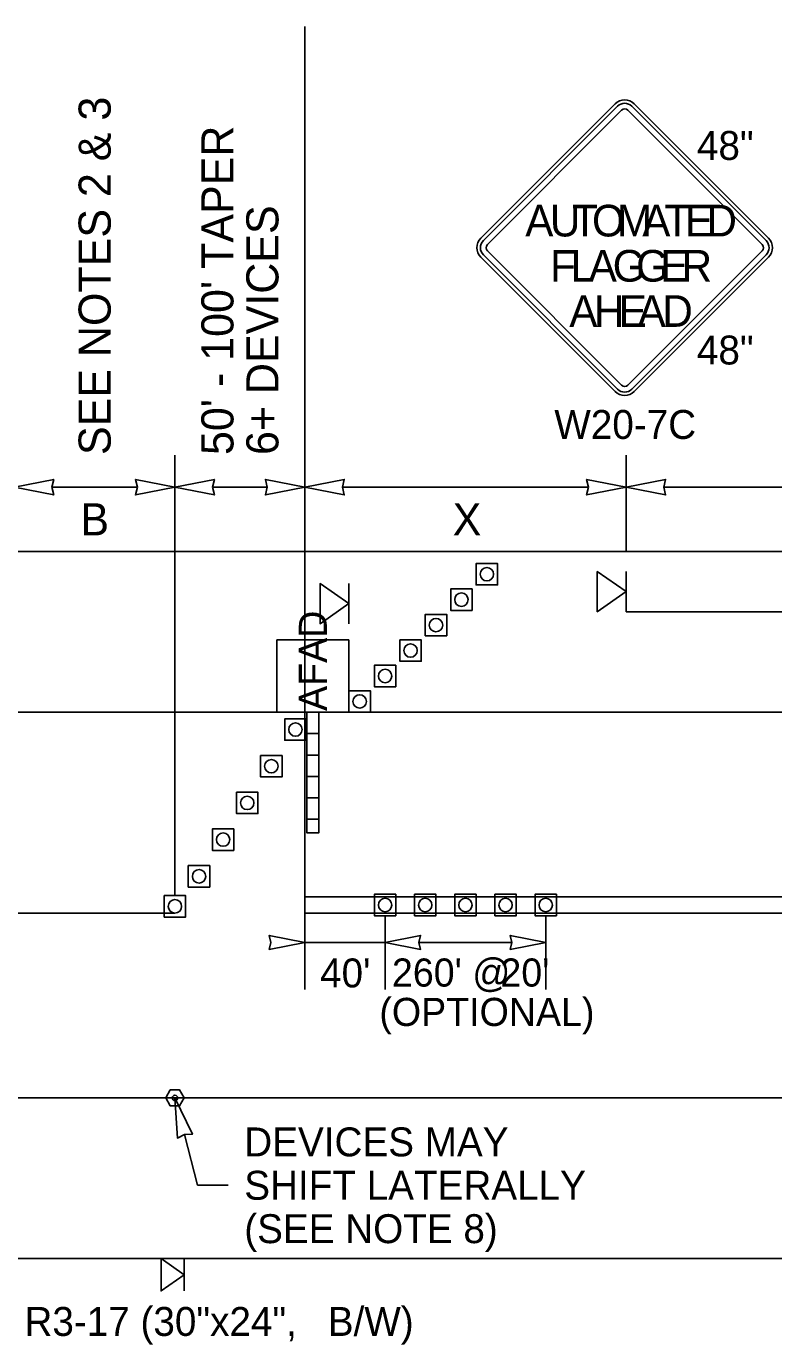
# Model space of a CAD drawing. Extents: x 99999.1 to 100095.7, y 99995 to 100010.7.
# Drawn here: x 100050.78 to 100052.641, y 100005.518 to 100008.799 of the extents above; entities that cross this region are included whole.
import ezdxf

# ---------------------------------------------------------------- set-up
doc = ezdxf.new("R2010")
doc.units = 0
for name, color, linetype in [('RD_ED_ShoulderPavedEdge', 7, 'Continuous'), ('RD_MK_LineDblYellowCenter', 7, 'Continuous'), ('RD_MK_LineEdgeWhite', 7, 'Continuous'), ('RD_MK_LineNoPass', 7, 'Continuous'), ('RD_MK_LineSkipCenter', 7, 'Continuous'), ('TR_SN_ConstructionSigns', 7, 'Continuous'), ('TR_WZ_AFAD', 7, 'Continuous'), ('TR_WZ_PortableSignMountBlk-Org', 7, 'Continuous'), ('TR_WZ_PortableSignMountBlk-Wht', 7, 'Continuous'), ('TR_WZ_TrafficCone', 7, 'Continuous'), ('TR_WZ_TubularMarker', 7, 'Continuous'), ('TR_WZ_WorkZoneDetails', 7, 'Continuous'), ('TR_WZ_WorkZoneTextCurrent', 7, 'Continuous')]:
    doc.layers.add(name, color=color, linetype=linetype)

msp = doc.modelspace()

# ---------------------------------------------------------------- linework, layer by layer
at = {"layer": 'RD_ED_ShoulderPavedEdge'}
for p, q in [((100040.1076, 100007.4923), (100055.6424, 100007.4923)), ((100040.1076, 100005.7323), (100055.6424, 100005.7323))]:
    msp.add_line(p, q, dxfattribs=at)
at = {"layer": 'RD_MK_LineDblYellowCenter'}
for p, q in [((100052.2733, 100006.6323), (100055.6631, 100006.6323)), ((100052.2733, 100006.5923), (100055.6218, 100006.5923))]:
    msp.add_line(p, q, dxfattribs=at)
at = {"layer": 'RD_MK_LineEdgeWhite'}
for p, q in [((100040.1076, 100007.0923), (100055.6424, 100007.0923)), ((100040.1076, 100006.1323), (100055.6424, 100006.1323))]:
    msp.add_line(p, q, dxfattribs=at)
at = {"layer": 'RD_MK_LineNoPass'}
msp.add_line((100051.4733, 100006.5923), (100052.2733, 100006.5923), dxfattribs=at)
at = {"layer": 'RD_MK_LineSkipCenter'}
for points in [[(100052.2733, 100006.6323), (100051.4733, 100006.6323)], [(100051.15, 100006.5923), (100043.4767, 100006.5923)]]:
    msp.add_lwpolyline(points, dxfattribs=at)
at = {"layer": 'TR_SN_ConstructionSigns'}
for p, q in [((100052.2461, 100008.6062), (100051.912, 100008.2721)), ((100052.2521, 100008.6002), (100051.918, 100008.2661)), ((100051.9279, 100008.2561), (100052.262, 100008.5903)), ((100052.2779, 100008.5903), (100052.612, 100008.2561)), ((100052.622, 100008.2661), (100052.2879, 100008.6002)), ((100052.6279, 100008.2721), (100052.2938, 100008.6062)), ((100051.918, 100008.2303), (100052.2521, 100007.8962)), ((100052.262, 100007.9061), (100051.9279, 100008.2402)), ((100052.612, 100008.2402), (100052.2779, 100007.9061)), ((100052.2879, 100007.8962), (100052.622, 100008.2303)), ((100051.912, 100008.2243), (100052.2461, 100007.8902)), ((100052.2938, 100007.8902), (100052.6279, 100008.2243))]:
    msp.add_line(p, q, dxfattribs=at)
for centre, radius, start, end in [((100052.27, 100008.5823), 0.0338, 45, 135), ((100052.27, 100008.5823), 0.0253, 45, 135), ((100052.27, 100008.5823), 0.0113, 45, 135), ((100051.9359, 100008.2482), 0.0338, 135, 225), ((100051.9359, 100008.2482), 0.0253, 135, 225), ((100052.6041, 100008.2482), 0.0253, 315, 45), ((100052.6041, 100008.2482), 0.0338, 315, 45), ((100051.9359, 100008.2482), 0.0113, 135, 225), ((100052.6041, 100008.2482), 0.0113, 315, 45), ((100052.27, 100007.9141), 0.0113, 225, 315), ((100052.27, 100007.9141), 0.0338, 225, 315), ((100052.27, 100007.9141), 0.0253, 225, 315)]:
    msp.add_arc(centre, radius, start, end, dxfattribs=at)
at = {"layer": 'TR_WZ_AFAD'}
for p, q in [((100051.4033, 100007.0923), (100051.4033, 100007.2723)), ((100051.4033, 100007.2723), (100051.5833, 100007.2723)), ((100051.5833, 100007.2723), (100051.4033, 100007.2723)), ((100051.4033, 100007.2723), (100051.4033, 100007.0923)), ((100051.5833, 100007.2723), (100051.5833, 100007.0923)), ((100051.5833, 100007.0923), (100051.5833, 100007.2723)), ((100051.5833, 100007.0923), (100051.4033, 100007.0923)), ((100051.5, 100007.0923), (100051.4933, 100007.0923)), ((100051.5, 100007.0923), (100051.5833, 100007.0923)), ((100051.5083, 100007.0923), (100051.5, 100007.0923)), ((100051.5083, 100007.039), (100051.5083, 100007.0923)), ((100051.4783, 100007.039), (100051.4783, 100006.9857)), ((100051.5083, 100006.9857), (100051.5083, 100007.039)), ((100051.4783, 100006.9857), (100051.4783, 100006.9323)), ((100051.4783, 100006.9857), (100051.4933, 100006.9857)), ((100051.4933, 100006.9857), (100051.5083, 100006.9857)), ((100051.5083, 100006.9323), (100051.5083, 100006.9857)), ((100051.4933, 100006.9323), (100051.4783, 100006.9323)), ((100051.4783, 100006.9323), (100051.4783, 100006.879)), ((100051.5083, 100006.9323), (100051.4933, 100006.9323)), ((100051.5083, 100006.879), (100051.5083, 100006.9323)), ((100051.4783, 100006.879), (100051.4783, 100006.8257)), ((100051.4783, 100006.879), (100051.4933, 100006.879)), ((100051.4933, 100006.879), (100051.5083, 100006.879)), ((100051.5083, 100006.8257), (100051.5083, 100006.879)), ((100051.4933, 100006.8257), (100051.4783, 100006.8257)), ((100051.4783, 100006.8257), (100051.4783, 100006.7923)), ((100051.5083, 100006.8257), (100051.4933, 100006.8257))]:
    msp.add_line(p, q, dxfattribs=at)
for points in [[(100051.4033, 100007.0923), (100051.4867, 100007.0923), (100051.5, 100007.0923)], [(100051.4933, 100007.0923), (100051.4867, 100007.0923), (100051.4783, 100007.0923), (100051.4783, 100007.039)], [(100051.4783, 100007.0923), (100051.4783, 100006.7923), (100051.5083, 100006.7923), (100051.5083, 100007.0923)], [(100051.4783, 100007.039), (100051.4933, 100007.039), (100051.5083, 100007.039)], [(100051.5083, 100007.039), (100051.4933, 100007.039), (100051.4783, 100007.039)], [(100051.5083, 100006.9857), (100051.4933, 100006.9857), (100051.4783, 100006.9857)], [(100051.4783, 100006.9323), (100051.4933, 100006.9323), (100051.5083, 100006.9323)], [(100051.5083, 100006.879), (100051.4933, 100006.879), (100051.4783, 100006.879)], [(100051.4783, 100006.8257), (100051.4933, 100006.8257), (100051.5083, 100006.8257)], [(100051.4783, 100006.7923), (100051.5083, 100006.7923), (100051.5083, 100006.8257)]]:
    msp.add_lwpolyline(points, dxfattribs=at)
at = {"layer": 'TR_WZ_PortableSignMountBlk-Org'}
msp.add_line((100052.2733, 100007.4422), (100052.2733, 100007.3422), dxfattribs=at)
msp.add_lwpolyline([(100052.2733, 100007.3923), (100052.2015, 100007.3422), (100052.2015, 100007.4422)], close=True, dxfattribs=at)
at = {"layer": 'TR_WZ_PortableSignMountBlk-Wht'}
for p, q in [((100051.5833, 100007.4123), (100051.5833, 100007.3123)), ((100051.1733, 100005.6519), (100051.1733, 100005.7323))]:
    msp.add_line(p, q, dxfattribs=at)
for points in [[(100051.5833, 100007.3624), (100051.5115, 100007.3123), (100051.5115, 100007.4123)], [(100051.1733, 100005.692), (100051.1156, 100005.7323), (100051.1156, 100005.6519)]]:
    msp.add_lwpolyline(points, close=True, dxfattribs=at)
at = {"layer": 'TR_WZ_TrafficCone'}
for points in [[(100051.9533, 100007.4623), (100051.9, 100007.4623), (100051.9, 100007.409), (100051.9533, 100007.409), (100051.9533, 100007.4623)], [(100051.9533, 100007.409), (100051.9, 100007.409), (100051.9, 100007.4623), (100051.9533, 100007.4623), (100051.9533, 100007.409)], [(100051.89, 100007.399), (100051.8367, 100007.399), (100051.8367, 100007.3457), (100051.89, 100007.3457), (100051.89, 100007.399)], [(100051.89, 100007.3457), (100051.8367, 100007.3457), (100051.8367, 100007.399), (100051.89, 100007.399), (100051.89, 100007.3457)], [(100051.8267, 100007.3357), (100051.7733, 100007.3357), (100051.7733, 100007.2823), (100051.8267, 100007.2823), (100051.8267, 100007.3357)], [(100051.8267, 100007.2823), (100051.7733, 100007.2823), (100051.7733, 100007.3357), (100051.8267, 100007.3357), (100051.8267, 100007.2823)], [(100051.7633, 100007.219), (100051.71, 100007.219), (100051.71, 100007.2723), (100051.7633, 100007.2723), (100051.7633, 100007.219)], [(100051.7633, 100007.2723), (100051.71, 100007.2723), (100051.71, 100007.219), (100051.7633, 100007.219), (100051.7633, 100007.2723)], [(100051.7, 100007.1557), (100051.6467, 100007.1557), (100051.6467, 100007.209), (100051.7, 100007.209), (100051.7, 100007.1557)], [(100051.7, 100007.209), (100051.6467, 100007.209), (100051.6467, 100007.1557), (100051.7, 100007.1557), (100051.7, 100007.209)], [(100051.6367, 100007.0923), (100051.5833, 100007.0923), (100051.5833, 100007.1457), (100051.6367, 100007.1457), (100051.6367, 100007.0923)], [(100051.6367, 100007.1457), (100051.5833, 100007.1457), (100051.5833, 100007.0923), (100051.6367, 100007.0923), (100051.6367, 100007.1457)], [(100051.4766, 100007.0757), (100051.4233, 100007.0757), (100051.4233, 100007.0224), (100051.4766, 100007.0224), (100051.4766, 100007.0757)], [(100051.4766, 100007.0224), (100051.4233, 100007.0224), (100051.4233, 100007.0757), (100051.4766, 100007.0757), (100051.4766, 100007.0224)], [(100051.4166, 100006.9844), (100051.3633, 100006.9844), (100051.3633, 100006.9311), (100051.4166, 100006.9311), (100051.4166, 100006.9844)], [(100051.4166, 100006.9311), (100051.3633, 100006.9311), (100051.3633, 100006.9844), (100051.4166, 100006.9844), (100051.4166, 100006.9311)], [(100051.3566, 100006.8931), (100051.3033, 100006.8931), (100051.3033, 100006.8397), (100051.3566, 100006.8397), (100051.3566, 100006.8931)], [(100051.3566, 100006.8397), (100051.3033, 100006.8397), (100051.3033, 100006.8931), (100051.3566, 100006.8931), (100051.3566, 100006.8397)], [(100051.2966, 100006.8017), (100051.2433, 100006.8017), (100051.2433, 100006.7484), (100051.2966, 100006.7484), (100051.2966, 100006.8017)], [(100051.2966, 100006.7484), (100051.2433, 100006.7484), (100051.2433, 100006.8017), (100051.2966, 100006.8017), (100051.2966, 100006.7484)], [(100051.2366, 100006.7104), (100051.1833, 100006.7104), (100051.1833, 100006.6571), (100051.2366, 100006.6571), (100051.2366, 100006.7104)], [(100051.2366, 100006.6571), (100051.1833, 100006.6571), (100051.1833, 100006.7104), (100051.2366, 100006.7104), (100051.2366, 100006.6571)], [(100051.1766, 100006.6357), (100051.1233, 100006.6357), (100051.1233, 100006.5823), (100051.1766, 100006.5823), (100051.1766, 100006.6357)], [(100051.1766, 100006.5823), (100051.1233, 100006.5823), (100051.1233, 100006.6357), (100051.1766, 100006.6357), (100051.1766, 100006.5823)], [(100051.7, 100006.639), (100051.6467, 100006.639), (100051.6467, 100006.5857), (100051.7, 100006.5857), (100051.7, 100006.639)], [(100051.7, 100006.5857), (100051.6467, 100006.5857), (100051.6467, 100006.639), (100051.7, 100006.639), (100051.7, 100006.5857)], [(100051.8, 100006.639), (100051.7467, 100006.639), (100051.7467, 100006.5857), (100051.8, 100006.5857), (100051.8, 100006.639)], [(100051.8, 100006.5857), (100051.7467, 100006.5857), (100051.7467, 100006.639), (100051.8, 100006.639), (100051.8, 100006.5857)], [(100051.9, 100006.639), (100051.8467, 100006.639), (100051.8467, 100006.5857), (100051.9, 100006.5857), (100051.9, 100006.639)], [(100051.9, 100006.5857), (100051.8467, 100006.5857), (100051.8467, 100006.639), (100051.9, 100006.639), (100051.9, 100006.5857)], [(100052, 100006.639), (100051.9467, 100006.639), (100051.9467, 100006.5857), (100052, 100006.5857), (100052, 100006.639)], [(100052, 100006.5857), (100051.9467, 100006.5857), (100051.9467, 100006.639), (100052, 100006.639), (100052, 100006.5857)], [(100052.1, 100006.639), (100052.0467, 100006.639), (100052.0467, 100006.5857), (100052.1, 100006.5857), (100052.1, 100006.639)], [(100052.1, 100006.5857), (100052.0467, 100006.5857), (100052.0467, 100006.639), (100052.1, 100006.639), (100052.1, 100006.5857)]]:
    msp.add_lwpolyline(points, dxfattribs=at)
for centre in [(100051.9267, 100007.4357), (100051.8633, 100007.3723), (100051.8, 100007.309), (100051.7367, 100007.2457), (100051.6733, 100007.1823), (100051.61, 100007.119), (100051.45, 100007.0491), (100051.39, 100006.9577), (100051.33, 100006.8664), (100051.27, 100006.7751), (100051.21, 100006.6837), (100051.15, 100006.609), (100051.6733, 100006.6123), (100051.7733, 100006.6123), (100051.8733, 100006.6123), (100051.9733, 100006.6123), (100052.0733, 100006.6123)]:
    msp.add_circle(centre, 0.0167, dxfattribs=at)
at = {"layer": 'TR_WZ_TubularMarker'}
msp.add_lwpolyline([(100051.1269, 100006.1323), (100051.1384, 100006.1523), (100051.1615, 100006.1523), (100051.1731, 100006.1323), (100051.1615, 100006.1123), (100051.1384, 100006.1123)], close=True, dxfattribs=at)
msp.add_lwpolyline([(100051.1384, 100006.1123), (100051.1615, 100006.1123), (100051.1731, 100006.1323), (100051.1615, 100006.1523), (100051.1384, 100006.1523), (100051.1269, 100006.1323), (100051.1384, 100006.1123)], dxfattribs=at)
msp.add_circle((100051.15, 100006.1323), 0.00667, dxfattribs=at)
at = {"layer": 'TR_WZ_WorkZoneDetails'}
for p, q in [((100051.4733, 100007.0923), (100051.4733, 100008.7991)), ((100051.15, 100006.6357), (100051.15, 100007.7323)), ((100052.2733, 100007.4923), (100052.2733, 100007.7323)), ((100051.0563, 100007.6523), (100050.8437, 100007.6523)), ((100051.3796, 100007.6523), (100051.2437, 100007.6523)), ((100051.5671, 100007.6523), (100052.1796, 100007.6523)), ((100052.3671, 100007.6523), (100052.9796, 100007.6523)), ((100052.2733, 100007.3422), (100054.6733, 100007.3422)), ((100051.4733, 100007.0923), (100051.4733, 100006.4023)), ((100051.6733, 100006.5857), (100051.6733, 100006.4023)), ((100052.0733, 100006.5857), (100052.0733, 100006.4023)), ((100051.6733, 100006.5193), (100051.4733, 100006.5193)), ((100051.989, 100006.5193), (100051.7577, 100006.5193)), ((100051.1735, 100006.0416), (100051.2064, 100005.9148)), ((100051.2826, 100005.9148), (100051.2064, 100005.9148))]:
    msp.add_line(p, q, dxfattribs=at)
for points in [[(100050.75, 100007.6523), (100050.8483, 100007.6331), (100050.8437, 100007.6523), (100050.8483, 100007.6716)], [(100051.15, 100007.6523), (100051.0517, 100007.6331), (100051.0563, 100007.6523), (100051.0517, 100007.6716)], [(100051.15, 100007.6523), (100051.2483, 100007.6331), (100051.2437, 100007.6523), (100051.2483, 100007.6716)], [(100051.4733, 100007.6523), (100051.3751, 100007.6331), (100051.3796, 100007.6523), (100051.3751, 100007.6716)], [(100051.4733, 100007.6523), (100051.5716, 100007.6331), (100051.5671, 100007.6523), (100051.5716, 100007.6716)], [(100052.2733, 100007.6523), (100052.1751, 100007.6331), (100052.1796, 100007.6523), (100052.1751, 100007.6716)], [(100052.2733, 100007.6523), (100052.3716, 100007.6331), (100052.3671, 100007.6523), (100052.3716, 100007.6716)], [(100051.4733, 100006.5193), (100051.3849, 100006.502), (100051.389, 100006.5193), (100051.3849, 100006.5367)], [(100051.6733, 100006.5193), (100051.7618, 100006.502), (100051.7577, 100006.5193), (100051.7618, 100006.5367)], [(100052.0733, 100006.5193), (100051.9849, 100006.502), (100051.989, 100006.5193), (100051.9849, 100006.5367)], [(100051.15, 100006.1323), (100051.1933, 100006.042), (100051.1735, 100006.0416), (100051.156, 100006.0324)]]:
    msp.add_lwpolyline(points, close=True, dxfattribs=at)

# ---------------------------------------------------------------- texts
at = {"layer": 'TR_SN_ConstructionSigns'}
for s, p in [('48"', (100052.4498, 100008.4667)), ('48"', (100052.4498, 100007.9576)), ('W20-7C', (100052.0947, 100007.7723))]:
    msp.add_text(s, height=0.072, rotation=360, dxfattribs=at).set_placement(p)
for s, p in [('A', (100052.0223, 100008.2763)), ('U', (100052.0837, 100008.2763)), ('T', (100052.1388, 100008.2763)), ('O', (100052.1885, 100008.2763)), ('M', (100052.2507, 100008.2763)), ('A', (100052.3137, 100008.2763)), ('T', (100052.3688, 100008.2763)), ('E', (100052.42, 100008.2763)), ('D', (100052.4735, 100008.2763)), ('F', (100052.0841, 100008.1638)), ('L', (100052.1353, 100008.1638)), ('A', (100052.1802, 100008.1638)), ('G', (100052.24, 100008.1638)), ('G', (100052.2983, 100008.1638)), ('E', (100052.3582, 100008.1638)), ('R', (100052.4117, 100008.1638)), ('A', (100052.1321, 100008.0513)), ('H', (100052.1936, 100008.0513)), ('E', (100052.255, 100008.0513)), ('A', (100052.3022, 100008.0513)), ('D', (100052.3637, 100008.0513))]:
    msp.add_text(s, height=0.0787, dxfattribs=at).set_placement(p)
at = {"layer": 'TR_WZ_AFAD'}
msp.add_text('AFAD', height=0.07, rotation=90, dxfattribs=at).set_placement((100051.5283, 100007.0953))
at = {"layer": 'TR_WZ_WorkZoneDetails'}
for s, p in [('R3-17 (30"x24",', (100050.7752, 100005.5399)), ('B/W)', (100051.5306, 100005.5399))]:
    msp.add_text(s, height=0.072, rotation=360, dxfattribs=at).set_placement(p)
at = {"layer": 'TR_WZ_WorkZoneTextCurrent'}
for s, p in [('SEE NOTES 2 & 3', (100050.99, 100007.7323)), ("50' - 100' TAPER", (100051.2957, 100007.7323)), ('6+ DEVICES', (100051.4077, 100007.7323))]:
    msp.add_text(s, height=0.08, rotation=90, dxfattribs=at).set_placement(p)
for s, height, p in [('B', 0.08, (100050.9145, 100007.5323)), ('X', 0.08, (100051.8416, 100007.5323)), ("40'", 0.072, (100051.5114, 100006.4073)), ("260' @", 0.07, (100051.6903, 100006.4093)), ("20'", 0.07, (100051.9604, 100006.4093)), ('(OPTIONAL)', 0.07, (100051.659, 100006.3113)), ('DEVICES MAY', 0.072, (100051.3226, 100005.9868)), ('SHIFT LATERALLY', 0.072, (100051.3226, 100005.8788)), ('(SEE NOTE 8)', 0.072, (100051.3226, 100005.7708))]:
    msp.add_text(s, height=height, dxfattribs=at).set_placement(p)

doc.saveas('drawing.dxf')
